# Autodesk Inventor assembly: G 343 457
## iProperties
Company: Mayer & Müller AG Schaltgeräte
Created: 2005-10
Part Number: G 343 457
Document SubType Name: Schweißkonstruktion
Designer: I.Baliuc
Manufacturer: Standard
Standards Organization: Custom
Description: Rohrtraverse, kompl.
Mass: 7997.43 g
Surface Area: 3298.06 cm^2
Volume: 1019.9 cm^3
Density: 7.84138 g/cm^3
Zweck: Trenner 3-polig
Author: T.Messerschmitt
Revision Number: 343457
